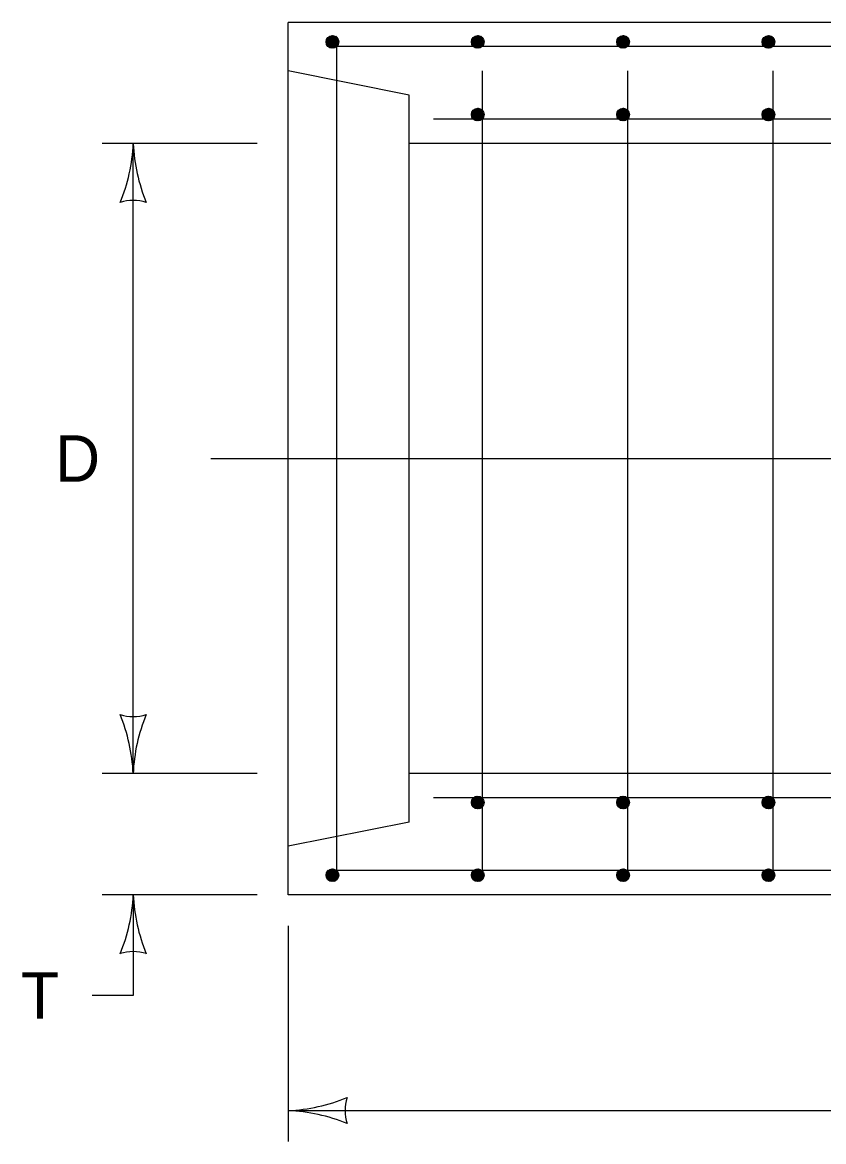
# Model space of a CAD drawing. Extents: x 49991.4 to 50021, y 49987.6 to 50011.4.
# Drawn here: x 50008.838 to 50009.872, y 49996.216 to 49997.66 of the extents above; entities that cross this region are included whole.
import ezdxf

# ---------------------------------------------------------------- set-up
doc = ezdxf.new("R2010")
doc.units = 0
for name, color, linetype in [('Level 1', 7, 'Continuous'), ('Level 2', 7, 'Continuous'), ('Level 3', 7, 'Continuous'), ('Level 5', 7, 'Continuous')]:
    doc.layers.add(name, color=color, linetype=linetype)

msp = doc.modelspace()

# ---------------------------------------------------------------- linework, layer by layer
at = {"layer": 'Level 1'}
for p, q in [((50012.0261, 49997.6602), (50009.1807, 49997.6602)), ((50009.1807, 49996.5345), (50009.1807, 49997.6602)), ((50009.2433, 49997.6351), (50009.2433, 49996.5658)), ((50011.9745, 49997.629), (50009.2433, 49997.629)), ((50009.1807, 49997.5976), (50009.1807, 49997.5976)), ((50009.337, 49997.5663), (50009.1807, 49997.5976)), ((50009.4309, 49997.5976), (50009.4309, 49996.5658)), ((50009.6185, 49997.5976), (50009.6185, 49996.5658)), ((50009.8061, 49997.5976), (50009.8061, 49996.5658)), ((50009.337, 49996.6283), (50009.337, 49997.5663)), ((50012.1468, 49997.5351), (50009.3683, 49997.5351)), ((50012.1825, 49997.5038), (50009.337, 49997.5038)), ((50012.1825, 49996.6909), (50009.337, 49996.6909)), ((50012.1468, 49996.6596), (50009.3683, 49996.6596)), ((50009.337, 49996.6283), (50009.1807, 49996.597)), ((50009.1807, 49996.597), (50009.1807, 49996.597)), ((50011.9745, 49996.5658), (50009.2433, 49996.5658)), ((50012.0261, 49996.5345), (50009.1807, 49996.5345))]:
    msp.add_line(p, q, dxfattribs=at)
for points in [[(50009.2298, 49997.6369), (50009.2396, 49997.627)], [(50009.2302, 49997.6379), (50009.2406, 49997.6274)], [(50009.2306, 49997.6388), (50009.2416, 49997.6278)], [(50009.231, 49997.6396), (50009.2424, 49997.6282)], [(50009.2316, 49997.6405), (50009.2316, 49997.6404), (50009.2431, 49997.6288), (50009.2432, 49997.6288)], [(50009.2322, 49997.641), (50009.2322, 49997.641), (50009.2438, 49997.6295), (50009.2438, 49997.6295)], [(50009.233, 49997.6416), (50009.2444, 49997.6302)], [(50009.2338, 49997.6422), (50009.245, 49997.631)], [(50009.2347, 49997.6426), (50009.2454, 49997.6319)], [(50009.2357, 49997.643), (50009.2457, 49997.633)], [(50009.2368, 49997.6432), (50009.2459, 49997.6341)], [(50009.2382, 49997.6432), (50009.2459, 49997.6353)], [(50009.2396, 49997.643), (50009.2458, 49997.6369)], [(50009.2418, 49997.6422), (50009.245, 49997.639)], [(50009.4174, 49997.6369), (50009.4272, 49997.627)], [(50009.4178, 49997.6379), (50009.4282, 49997.6274)], [(50009.4182, 49997.6388), (50009.4292, 49997.6278)], [(50009.4186, 49997.6396), (50009.43, 49997.6282)], [(50009.4192, 49997.6405), (50009.4192, 49997.6404), (50009.4307, 49997.6288), (50009.4308, 49997.6288)], [(50009.4198, 49997.641), (50009.4198, 49997.641), (50009.4314, 49997.6295), (50009.4314, 49997.6295)], [(50009.4206, 49997.6416), (50009.432, 49997.6302)], [(50009.4214, 49997.6422), (50009.4326, 49997.631)], [(50009.4223, 49997.6426), (50009.433, 49997.6319)], [(50009.4233, 49997.643), (50009.4333, 49997.633)], [(50009.4244, 49997.6432), (50009.4335, 49997.6341)], [(50009.4258, 49997.6432), (50009.4335, 49997.6353)], [(50009.4272, 49997.643), (50009.4334, 49997.6369)], [(50009.4294, 49997.6422), (50009.4326, 49997.639)], [(50009.605, 49997.6369), (50009.6149, 49997.627)], [(50009.6054, 49997.6379), (50009.6158, 49997.6274)], [(50009.6058, 49997.6388), (50009.6168, 49997.6278)], [(50009.6063, 49997.6396), (50009.6176, 49997.6282)], [(50009.6068, 49997.6405), (50009.6069, 49997.6404), (50009.6183, 49997.6288), (50009.6184, 49997.6288)], [(50009.6074, 49997.641), (50009.6074, 49997.641), (50009.619, 49997.6295), (50009.619, 49997.6295)], [(50009.6082, 49997.6416), (50009.6196, 49997.6302)], [(50009.609, 49997.6422), (50009.6202, 49997.631)], [(50009.6099, 49997.6426), (50009.6206, 49997.6319)], [(50009.6109, 49997.643), (50009.6209, 49997.633)], [(50009.612, 49997.6432), (50009.6211, 49997.6341)], [(50009.6134, 49997.6432), (50009.6212, 49997.6353)], [(50009.6149, 49997.643), (50009.621, 49997.6369)], [(50009.617, 49997.6422), (50009.6202, 49997.639)], [(50009.7926, 49997.6369), (50009.8025, 49997.627)], [(50009.793, 49997.6379), (50009.8034, 49997.6274)], [(50009.7934, 49997.6388), (50009.8044, 49997.6278)], [(50009.7939, 49997.6396), (50009.8052, 49997.6282)], [(50009.7944, 49997.6405), (50009.7945, 49997.6404), (50009.8059, 49997.6288), (50009.806, 49997.6288)], [(50009.795, 49997.641), (50009.795, 49997.641), (50009.8066, 49997.6295), (50009.8066, 49997.6295)], [(50009.7958, 49997.6416), (50009.8072, 49997.6302)], [(50009.7966, 49997.6422), (50009.8078, 49997.631)], [(50009.7975, 49997.6426), (50009.8082, 49997.6319)], [(50009.7985, 49997.643), (50009.8086, 49997.633)], [(50009.7997, 49997.6432), (50009.8087, 49997.6341)], [(50009.801, 49997.6432), (50009.8088, 49997.6353)], [(50009.8025, 49997.643), (50009.8086, 49997.6369)], [(50009.8046, 49997.6422), (50009.8078, 49997.639)], [(50009.2296, 49997.6357), (50009.2385, 49997.6269)], [(50009.2297, 49997.6344), (50009.2371, 49997.6269)], [(50009.2299, 49997.6327), (50009.2355, 49997.6272)], [(50009.2313, 49997.6301), (50009.2327, 49997.6286), (50009.2329, 49997.6285)], [(50009.4172, 49997.6357), (50009.4261, 49997.6269)], [(50009.4173, 49997.6344), (50009.4247, 49997.6269)], [(50009.4175, 49997.6327), (50009.4231, 49997.6272)], [(50009.419, 49997.6301), (50009.4204, 49997.6286), (50009.4205, 49997.6285)], [(50009.6049, 49997.6357), (50009.6137, 49997.6269)], [(50009.6049, 49997.6344), (50009.6123, 49997.6269)], [(50009.6051, 49997.6327), (50009.6107, 49997.6272)], [(50009.6066, 49997.6301), (50009.608, 49997.6286), (50009.6081, 49997.6285)], [(50009.7925, 49997.6357), (50009.8013, 49997.6269)], [(50009.7925, 49997.6344), (50009.7999, 49997.6269)], [(50009.7928, 49997.6327), (50009.7983, 49997.6272)], [(50009.7942, 49997.6301), (50009.7956, 49997.6286), (50009.7957, 49997.6285)], [(50009.4172, 49997.5419), (50009.4261, 49997.533)], [(50009.4173, 49997.5406), (50009.4247, 49997.533)], [(50009.4174, 49997.543), (50009.4272, 49997.5333)], [(50009.4175, 49997.539), (50009.4231, 49997.5334)], [(50009.4178, 49997.5441), (50009.4282, 49997.5336)], [(50009.4182, 49997.545), (50009.4292, 49997.5339)], [(50009.4186, 49997.5458), (50009.43, 49997.5345)], [(50009.419, 49997.5362), (50009.4204, 49997.5347), (50009.4205, 49997.5347)], [(50009.4192, 49997.5466), (50009.4192, 49997.5466), (50009.4307, 49997.535), (50009.4308, 49997.535)], [(50009.4198, 49997.5473), (50009.4198, 49997.5473), (50009.4314, 49997.5357), (50009.4314, 49997.5357)], [(50009.4206, 49997.5478), (50009.432, 49997.5365)], [(50009.4214, 49997.5484), (50009.4326, 49997.5373)], [(50009.4223, 49997.5488), (50009.433, 49997.5382)], [(50009.4233, 49997.5491), (50009.4333, 49997.5391)], [(50009.4244, 49997.5494), (50009.4335, 49997.5402)], [(50009.4258, 49997.5494), (50009.4335, 49997.5415)], [(50009.4272, 49997.5492), (50009.4334, 49997.543)], [(50009.4294, 49997.5484), (50009.4326, 49997.5452)], [(50009.6049, 49997.5419), (50009.6137, 49997.533)], [(50009.6049, 49997.5406), (50009.6123, 49997.533)], [(50009.605, 49997.543), (50009.6149, 49997.5333)], [(50009.6051, 49997.539), (50009.6107, 49997.5334)], [(50009.6054, 49997.5441), (50009.6158, 49997.5336)], [(50009.6058, 49997.545), (50009.6168, 49997.5339)], [(50009.6063, 49997.5458), (50009.6176, 49997.5345)], [(50009.6066, 49997.5362), (50009.608, 49997.5347), (50009.6081, 49997.5347)], [(50009.6068, 49997.5466), (50009.6069, 49997.5466), (50009.6183, 49997.535), (50009.6184, 49997.535)], [(50009.6074, 49997.5473), (50009.6074, 49997.5473), (50009.619, 49997.5357), (50009.619, 49997.5357)], [(50009.6082, 49997.5478), (50009.6196, 49997.5365)], [(50009.609, 49997.5484), (50009.6202, 49997.5373)], [(50009.6099, 49997.5488), (50009.6206, 49997.5382)], [(50009.6109, 49997.5491), (50009.6209, 49997.5391)], [(50009.612, 49997.5494), (50009.6211, 49997.5402)], [(50009.6134, 49997.5494), (50009.6212, 49997.5415)], [(50009.6149, 49997.5492), (50009.621, 49997.543)], [(50009.617, 49997.5484), (50009.6202, 49997.5452)], [(50009.7925, 49997.5419), (50009.8013, 49997.533)], [(50009.7925, 49997.5406), (50009.7999, 49997.533)], [(50009.7926, 49997.543), (50009.8025, 49997.5333)], [(50009.7928, 49997.539), (50009.7983, 49997.5334)], [(50009.793, 49997.5441), (50009.8034, 49997.5336)], [(50009.7934, 49997.545), (50009.8044, 49997.5339)], [(50009.7939, 49997.5458), (50009.8052, 49997.5345)], [(50009.7942, 49997.5362), (50009.7956, 49997.5347), (50009.7957, 49997.5347)], [(50009.7944, 49997.5466), (50009.7945, 49997.5466), (50009.8059, 49997.535), (50009.806, 49997.535)], [(50009.795, 49997.5473), (50009.795, 49997.5473), (50009.8066, 49997.5357), (50009.8066, 49997.5357)], [(50009.7958, 49997.5478), (50009.8072, 49997.5365)], [(50009.7966, 49997.5484), (50009.8078, 49997.5373)], [(50009.7975, 49997.5488), (50009.8082, 49997.5382)], [(50009.7985, 49997.5491), (50009.8086, 49997.5391)], [(50009.7997, 49997.5494), (50009.8087, 49997.5402)], [(50009.801, 49997.5494), (50009.8088, 49997.5415)], [(50009.8025, 49997.5492), (50009.8086, 49997.543)], [(50009.8046, 49997.5484), (50009.8078, 49997.5452)], [(50009.4172, 49996.6528), (50009.4261, 49996.6617)], [(50009.4173, 49996.6542), (50009.4247, 49996.6617)], [(50009.4174, 49996.6517), (50009.4272, 49996.6614)], [(50009.4175, 49996.6558), (50009.4231, 49996.6614)], [(50009.4178, 49996.6506), (50009.4282, 49996.6611)], [(50009.4182, 49996.6497), (50009.4292, 49996.6608)], [(50009.4186, 49996.6489), (50009.43, 49996.6602)], [(50009.419, 49996.6585), (50009.4204, 49996.66), (50009.4205, 49996.66)], [(50009.4192, 49996.6481), (50009.4192, 49996.6482), (50009.4307, 49996.6597), (50009.4308, 49996.6597)], [(50009.4198, 49996.6474), (50009.4198, 49996.6474), (50009.4314, 49996.659), (50009.4314, 49996.659)], [(50009.4206, 49996.6469), (50009.432, 49996.6582)], [(50009.4214, 49996.6463), (50009.4326, 49996.6574)], [(50009.4223, 49996.6459), (50009.433, 49996.6566)], [(50009.4233, 49996.6456), (50009.4333, 49996.6556)], [(50009.4244, 49996.6454), (50009.4335, 49996.6545)], [(50009.6049, 49996.6542), (50009.6123, 49996.6617)], [(50009.6049, 49996.6528), (50009.6137, 49996.6617)], [(50009.605, 49996.6517), (50009.6149, 49996.6614)], [(50009.6051, 49996.6558), (50009.6107, 49996.6614)], [(50009.6054, 49996.6506), (50009.6158, 49996.6611)], [(50009.6058, 49996.6497), (50009.6168, 49996.6608)], [(50009.6063, 49996.6489), (50009.6176, 49996.6602)], [(50009.6066, 49996.6585), (50009.608, 49996.66), (50009.6081, 49996.66)], [(50009.6068, 49996.6481), (50009.6069, 49996.6482), (50009.6183, 49996.6597), (50009.6184, 49996.6597)], [(50009.6074, 49996.6474), (50009.6074, 49996.6474), (50009.619, 49996.659), (50009.619, 49996.659)], [(50009.6082, 49996.6469), (50009.6196, 49996.6582)], [(50009.609, 49996.6463), (50009.6202, 49996.6574)], [(50009.6099, 49996.6459), (50009.6206, 49996.6566)], [(50009.6109, 49996.6456), (50009.6209, 49996.6556)], [(50009.612, 49996.6454), (50009.6211, 49996.6545)], [(50009.7925, 49996.6542), (50009.7999, 49996.6617)], [(50009.7925, 49996.6528), (50009.8013, 49996.6617)], [(50009.7926, 49996.6517), (50009.8025, 49996.6614)], [(50009.7928, 49996.6558), (50009.7983, 49996.6614)], [(50009.793, 49996.6506), (50009.8034, 49996.6611)], [(50009.7934, 49996.6497), (50009.8044, 49996.6608)], [(50009.7939, 49996.6489), (50009.8052, 49996.6602)], [(50009.7942, 49996.6585), (50009.7956, 49996.66), (50009.7957, 49996.66)], [(50009.7944, 49996.6481), (50009.7945, 49996.6482), (50009.8059, 49996.6597), (50009.806, 49996.6597)], [(50009.795, 49996.6474), (50009.795, 49996.6474), (50009.8066, 49996.659), (50009.8066, 49996.659)], [(50009.7958, 49996.6469), (50009.8072, 49996.6582)], [(50009.7966, 49996.6463), (50009.8078, 49996.6574)], [(50009.7975, 49996.6459), (50009.8082, 49996.6566)], [(50009.7985, 49996.6456), (50009.8086, 49996.6556)], [(50009.7997, 49996.6454), (50009.8087, 49996.6545)], [(50009.4258, 49996.6454), (50009.4335, 49996.6532)], [(50009.4272, 49996.6455), (50009.4334, 49996.6517)], [(50009.4294, 49996.6463), (50009.4326, 49996.6495)], [(50009.6134, 49996.6454), (50009.6212, 49996.6532)], [(50009.6149, 49996.6455), (50009.621, 49996.6517)], [(50009.617, 49996.6463), (50009.6202, 49996.6495)], [(50009.801, 49996.6454), (50009.8088, 49996.6532)], [(50009.8025, 49996.6455), (50009.8086, 49996.6517)], [(50009.8046, 49996.6463), (50009.8078, 49996.6495)], [(50009.2296, 49996.559), (50009.2385, 49996.5678)], [(50009.2297, 49996.5603), (50009.2371, 49996.5678)], [(50009.2298, 49996.5578), (50009.2396, 49996.5677)], [(50009.4172, 49996.559), (50009.4261, 49996.5678)], [(50009.4173, 49996.5603), (50009.4247, 49996.5678)], [(50009.4174, 49996.5578), (50009.4272, 49996.5677)], [(50009.6049, 49996.5603), (50009.6123, 49996.5678)], [(50009.6049, 49996.559), (50009.6137, 49996.5678)], [(50009.605, 49996.5578), (50009.6149, 49996.5677)], [(50009.7925, 49996.5603), (50009.7999, 49996.5678)], [(50009.7925, 49996.559), (50009.8013, 49996.5678)], [(50009.7926, 49996.5578), (50009.8025, 49996.5677)], [(50009.2299, 49996.562), (50009.2355, 49996.5675)], [(50009.2302, 49996.5568), (50009.2406, 49996.5674)], [(50009.2306, 49996.5559), (50009.2416, 49996.567)], [(50009.231, 49996.5551), (50009.2424, 49996.5665)], [(50009.2313, 49996.5646), (50009.2327, 49996.5662), (50009.2329, 49996.5662)], [(50009.2316, 49996.5542), (50009.2316, 49996.5543), (50009.2431, 49996.5659), (50009.2432, 49996.5659)], [(50009.2322, 49996.5537), (50009.2322, 49996.5537), (50009.2438, 49996.5652), (50009.2438, 49996.5652)], [(50009.233, 49996.5531), (50009.2444, 49996.5645)], [(50009.2338, 49996.5526), (50009.245, 49996.5637)], [(50009.2347, 49996.5521), (50009.2454, 49996.5628)], [(50009.2357, 49996.5518), (50009.2457, 49996.5618)], [(50009.2368, 49996.5515), (50009.2459, 49996.5606)], [(50009.2382, 49996.5515), (50009.2459, 49996.5594)], [(50009.2396, 49996.5517), (50009.2458, 49996.5578)], [(50009.2418, 49996.5526), (50009.245, 49996.5557)], [(50009.4175, 49996.562), (50009.4231, 49996.5675)], [(50009.4178, 49996.5568), (50009.4282, 49996.5674)], [(50009.4182, 49996.5559), (50009.4292, 49996.567)], [(50009.4186, 49996.5551), (50009.43, 49996.5665)], [(50009.419, 49996.5646), (50009.4204, 49996.5662), (50009.4205, 49996.5662)], [(50009.4192, 49996.5542), (50009.4192, 49996.5543), (50009.4307, 49996.5659), (50009.4308, 49996.5659)], [(50009.4198, 49996.5537), (50009.4198, 49996.5537), (50009.4314, 49996.5652), (50009.4314, 49996.5652)], [(50009.4206, 49996.5531), (50009.432, 49996.5645)], [(50009.4214, 49996.5526), (50009.4326, 49996.5637)], [(50009.4223, 49996.5521), (50009.433, 49996.5628)], [(50009.4233, 49996.5518), (50009.4333, 49996.5618)], [(50009.4244, 49996.5515), (50009.4335, 49996.5606)], [(50009.4258, 49996.5515), (50009.4335, 49996.5594)], [(50009.4272, 49996.5517), (50009.4334, 49996.5578)], [(50009.4294, 49996.5526), (50009.4326, 49996.5557)], [(50009.6051, 49996.562), (50009.6107, 49996.5675)], [(50009.6054, 49996.5568), (50009.6158, 49996.5674)], [(50009.6058, 49996.5559), (50009.6168, 49996.567)], [(50009.6063, 49996.5551), (50009.6176, 49996.5665)], [(50009.6066, 49996.5646), (50009.608, 49996.5662), (50009.6081, 49996.5662)], [(50009.6068, 49996.5542), (50009.6069, 49996.5543), (50009.6183, 49996.5659), (50009.6184, 49996.5659)], [(50009.6074, 49996.5537), (50009.6074, 49996.5537), (50009.619, 49996.5652), (50009.619, 49996.5652)], [(50009.6082, 49996.5531), (50009.6196, 49996.5645)], [(50009.609, 49996.5526), (50009.6202, 49996.5637)], [(50009.6099, 49996.5521), (50009.6206, 49996.5628)], [(50009.6109, 49996.5518), (50009.6209, 49996.5618)], [(50009.612, 49996.5515), (50009.6211, 49996.5606)], [(50009.6134, 49996.5515), (50009.6212, 49996.5594)], [(50009.6149, 49996.5517), (50009.621, 49996.5578)], [(50009.617, 49996.5526), (50009.6202, 49996.5557)], [(50009.7928, 49996.562), (50009.7983, 49996.5675)], [(50009.793, 49996.5568), (50009.8034, 49996.5674)], [(50009.7934, 49996.5559), (50009.8044, 49996.567)], [(50009.7939, 49996.5551), (50009.8052, 49996.5665)], [(50009.7942, 49996.5646), (50009.7956, 49996.5662), (50009.7957, 49996.5662)], [(50009.7944, 49996.5542), (50009.7945, 49996.5543), (50009.8059, 49996.5659), (50009.806, 49996.5659)], [(50009.795, 49996.5537), (50009.795, 49996.5537), (50009.8066, 49996.5652), (50009.8066, 49996.5652)], [(50009.7958, 49996.5531), (50009.8072, 49996.5645)], [(50009.7966, 49996.5526), (50009.8078, 49996.5637)], [(50009.7975, 49996.5521), (50009.8082, 49996.5628)], [(50009.7985, 49996.5518), (50009.8086, 49996.5618)], [(50009.7997, 49996.5515), (50009.8087, 49996.5606)], [(50009.801, 49996.5515), (50009.8088, 49996.5594)], [(50009.8025, 49996.5517), (50009.8086, 49996.5578)], [(50009.8046, 49996.5526), (50009.8078, 49996.5557)]]:
    msp.add_lwpolyline(points, dxfattribs=at)
for centre in [(50009.2378, 49997.635), (50009.4254, 49997.635), (50009.613, 49997.635), (50009.8006, 49997.635), (50009.4254, 49997.5412), (50009.613, 49997.5412), (50009.8006, 49997.5412), (50009.4254, 49996.6535), (50009.613, 49996.6535), (50009.8006, 49996.6535), (50009.2378, 49996.5597), (50009.4254, 49996.5597), (50009.613, 49996.5597), (50009.8006, 49996.5597)]:
    msp.add_circle(centre, 0.00819, dxfattribs=at)
at = {"layer": 'Level 3'}
for p, q in [((50009.1407, 49997.5038), (50008.9407, 49997.5038)), ((50008.9807, 49996.6909), (50008.9807, 49997.5038)), ((50009.1407, 49996.6909), (50008.9407, 49996.6909)), ((50009.1407, 49996.5345), (50008.9407, 49996.5345)), ((50008.9807, 49996.5345), (50008.9807, 49996.4045)), ((50009.1807, 49996.4945), (50009.1807, 49996.2159)), ((50008.9807, 49996.4045), (50008.9279, 49996.4045)), ((50009.1807, 49996.2559), (50012.0261, 49996.2559))]:
    msp.add_line(p, q, dxfattribs=at)
for centre, radius, start, end in [((50008.7586, 49997.5129), 0.2223, 337.456, 357.6395), ((50008.7586, 49997.5129), 0.2223, 337.456, 357.6395), ((50009.2134, 49997.5153), 0.233, 182.8273, 202.0772), ((50009.2134, 49997.5153), 0.233, 182.8273, 202.0772), ((50008.9807, 49997.3756), 0.0548, 72.1388, 107.8612), ((50008.9807, 49997.3756), 0.0548, 72.1388, 107.8612), ((50008.9807, 49996.8191), 0.0548, 252.1388, 287.8612), ((50008.748, 49996.6794), 0.233, 2.8273, 22.0772), ((50009.2028, 49996.6817), 0.2223, 157.456, 177.6395), ((50008.7586, 49996.5436), 0.2223, 337.456, 357.6395), ((50009.2134, 49996.546), 0.233, 182.8273, 202.0772), ((50008.9807, 49996.4063), 0.0548, 72.1388, 107.8612), ((50009.1692, 49996.4886), 0.233, 272.8273, 292.0772), ((50009.3089, 49996.2559), 0.0548, 162.1388, 197.8612), ((50009.1716, 49996.0338), 0.2223, 67.456, 87.6395)]:
    msp.add_arc(centre, radius, start, end, dxfattribs=at)
at = {"layer": 'Level 5'}
msp.add_line((50009.0807, 49997.0973), (50012.2825, 49997.0973), dxfattribs=at)

# ---------------------------------------------------------------- texts
at = {"layer": 'Level 2'}
for s, p in [('D', (50008.88, 49997.0674)), ('T', (50008.8359, 49996.3745))]:
    msp.add_text(s, height=0.06, dxfattribs=at).set_placement(p)

doc.saveas('drawing.dxf')
